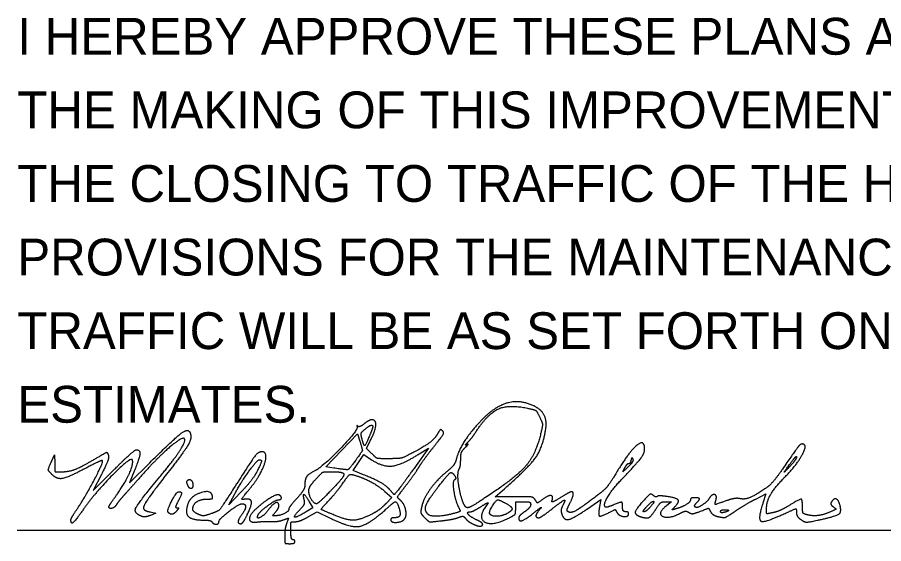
# Model space of a CAD drawing. Extents: x 0 to 34, y 0 to 22.
# Drawn here: x 24.528 to 27.822, y 8.875 to 10.877 of the extents above; entities that cross this region are included whole.
import ezdxf

# ---------------------------------------------------------------- set-up
doc = ezdxf.new("R2010")
doc.units = 0
for name, color, linetype in [('Default', 7, 'Continuous'), ('SH_Data', 7, 'Continuous'), ('SH_Text', 7, 'Continuous')]:
    doc.layers.add(name, color=color, linetype=linetype)

msp = doc.modelspace()

# ---------------------------------------------------------------- linework, layer by layer
at = {"layer": 'SH_Data'}
for p, q in [((24.5279, 10.875), (24.5279, 10.875)), ((24.5279, 8.9262), (28.0279, 8.9262))]:
    msp.add_line(p, q, dxfattribs=at)
at = {"layer": 'SH_Text'}
for p, q in [((26.8689, 9.1973), (26.8689, 9.1973)), ((25.1751, 9.0992), (25.1751, 9.0992)), ((25.1019, 8.9934), (25.1019, 8.9934)), ((24.7317, 8.9651), (24.7317, 8.9651))]:
    msp.add_line(p, q, dxfattribs=at)
for points in [[(25.7311, 9.1626), (25.7007, 9.1675), (25.8216, 9.2932), (25.8311, 9.2611)], [(25.875, 9.2176), (25.8551, 9.2374), (25.871, 9.2686)], [(26.0555, 9.216), (26.0906, 9.2382), (26.0439, 9.1722)], [(24.6592, 9.1901), (24.6697, 9.2129), (24.6703, 9.1806)], [(25.8445, 9.1369), (25.8042, 9.1532), (25.8247, 9.1836), (25.8451, 9.214), (25.8709, 9.1963)], [(24.9721, 9.1501), (24.9542, 9.1065), (25.0311, 9.1825)], [(24.8476, 9.1381), (24.8164, 9.0774), (24.8939, 9.1547)], [(25.3777, 9.0705), (25.3323, 9.0229), (25.3531, 9.0616)], [(25.9249, 9.0738), (25.9515, 9.0509), (25.9287, 9.0267)], [(26.4173, 9.0533), (26.3452, 9.0533), (26.3799, 9.0837)], [(27.3354, 9.0445), (27.3741, 9.0638), (27.3627, 9.029)], [(25.6378, 9.034), (25.6509, 9.011), (25.6264, 8.9961)], [(26.6962, 9.0079), (26.7465, 9.0423), (26.7416, 9.0164)], [(26.9947, 9.0341), (27.0155, 9.034), (26.9972, 9.0199)], [(25.0325, 8.9956), (25.0547, 8.9911), (25.0339, 8.9825)], [(25.6352, 8.9775), (25.6685, 8.9965), (25.7143, 8.9736)]]:
    msp.add_lwpolyline(points, dxfattribs=at)
for points in [[(26.2669, 9.2933), (26.314, 9.3669), (26.3945, 9.4057), (26.4679, 9.3901)], [(26.4949, 9.397), (26.4381, 9.4254), (26.3327, 9.3913), (26.2751, 9.3257)], [(26.4679, 9.3901), (26.4955, 9.3842), (26.5034, 9.3783), (26.5139, 9.3563)], [(26.5366, 9.3079), (26.542, 9.3407), (26.522, 9.3834), (26.4949, 9.397)], [(26.5139, 9.3563), (26.5247, 9.3335), (26.5252, 9.324), (26.5176, 9.2922)], [(25.8227, 9.3215), (25.8197, 9.3245), (25.8184, 9.3232), (25.8198, 9.3187)], [(25.8472, 9.331), (25.8367, 9.3227), (25.8257, 9.3185), (25.8227, 9.3215)], [(25.8765, 9.3459), (25.8708, 9.3459), (25.8576, 9.3392), (25.8472, 9.331)], [(25.8492, 9.3097), (25.8651, 9.3225), (25.8793, 9.3272), (25.8793, 9.3195)], [(25.871, 9.2686), (25.8893, 9.3044), (25.8923, 9.3459), (25.8765, 9.3459)], [(26.2751, 9.3257), (26.2415, 9.2876), (26.2035, 9.2238), (26.1959, 9.1927)], [(25.0311, 9.1825), (25.1255, 9.2758), (25.178, 9.3147), (25.1849, 9.2966)], [(25.1849, 9.2966), (25.1918, 9.2786), (25.1698, 9.2353), (25.123, 9.1749)], [(25.8198, 9.3187), (25.8234, 9.3069), (25.6903, 9.1681), (25.661, 9.1531)], [(25.8378, 9.2755), (25.8337, 9.2915), (25.8363, 9.2992), (25.8492, 9.3097)], [(25.8793, 9.3195), (25.8793, 9.3175), (25.8738, 9.3021), (25.8671, 9.2853)], [(26.1292, 9.2983), (26.1161, 9.2751), (26.0829, 9.2484), (26.0354, 9.2229)], [(26.114, 9.2467), (26.1419, 9.2815), (26.1508, 9.2978), (26.145, 9.3036)], [(26.145, 9.3036), (26.1391, 9.3094), (26.1346, 9.3078), (26.1292, 9.2983)], [(26.2403, 9.2602), (26.2487, 9.2686), (26.2606, 9.2835), (26.2669, 9.2933)], [(26.5176, 9.2922), (26.4987, 9.2135), (26.4222, 9.1255), (26.3058, 9.0486)], [(26.3799, 9.0837), (26.4722, 9.1644), (26.5256, 9.2408), (26.5366, 9.3079)], [(25.1629, 9.2744), (25.1552, 9.2822), (25.0642, 9.2052), (25.0117, 9.1464)], [(25.0698, 9.1293), (25.124, 9.1947), (25.1704, 9.267), (25.1629, 9.2744)], [(25.8311, 9.2611), (25.8403, 9.2301), (25.8397, 9.2277), (25.8158, 9.1943)], [(25.8671, 9.2853), (25.8528, 9.2495), (25.8449, 9.2468), (25.8378, 9.2755)], [(26.2365, 9.2509), (26.2302, 9.2476), (26.232, 9.2518), (26.2403, 9.2602)], [(26.9129, 9.2333), (26.9129, 9.2746), (26.8512, 9.2215), (26.8003, 9.1364)], [(24.8939, 9.1547), (24.9365, 9.1972), (24.9756, 9.2319), (24.9807, 9.2319)], [(24.9807, 9.2319), (24.9954, 9.2319), (24.9918, 9.1977), (24.9721, 9.1501)], [(25.4579, 9.2243), (25.4439, 9.2243), (25.4181, 9.1907), (25.3504, 9.0846)], [(25.4529, 9.1444), (25.4717, 9.18), (25.4745, 9.2243), (25.4579, 9.2243)], [(26.0557, 9.1674), (26.0662, 9.1842), (26.0925, 9.2199), (26.114, 9.2467)], [(26.2136, 9.1955), (26.2137, 9.2147), (26.2192, 9.2291), (26.2308, 9.2403)], [(26.2308, 9.2403), (26.2402, 9.2495), (26.2428, 9.2542), (26.2365, 9.2509)], [(26.8208, 9.1141), (26.8801, 9.1761), (26.9129, 9.2186), (26.9129, 9.2333)], [(27.5192, 9.252), (27.5095, 9.2579), (27.4896, 9.2352), (27.437, 9.1585)], [(27.4482, 9.1302), (27.487, 9.1694), (27.5309, 9.2447), (27.5192, 9.252)], [(24.6608, 9.1367), (24.6457, 9.1518), (24.6454, 9.16), (24.6592, 9.1901)], [(24.6966, 9.1483), (24.7244, 9.1483), (24.7735, 9.1679), (24.8318, 9.2023)], [(24.7591, 9.0126), (24.7889, 9.0568), (24.856, 9.1862), (24.8515, 9.1907)], [(24.9659, 9.1919), (24.9627, 9.2086), (24.829, 9.0752), (24.7795, 9.0059)], [(24.8515, 9.1907), (24.8499, 9.1922), (24.823, 9.18), (24.7917, 9.1636)], [(24.8318, 9.2023), (24.8648, 9.2217), (24.8696, 9.2228), (24.8739, 9.2115)], [(24.8739, 9.2115), (24.8769, 9.2038), (24.8665, 9.1748), (24.8476, 9.1381)], [(24.9026, 9.056), (24.9355, 9.1017), (24.9693, 9.1743), (24.9659, 9.1919)], [(25.3531, 9.0616), (25.3775, 9.107), (25.4398, 9.1937), (25.448, 9.1938)], [(25.448, 9.1938), (25.4575, 9.194), (25.4545, 9.1797), (25.4384, 9.1481)], [(25.8158, 9.1943), (25.7898, 9.1581), (25.7809, 9.1547), (25.7311, 9.1626)], [(25.8709, 9.1963), (25.9152, 9.1661), (25.9894, 9.174), (26.0555, 9.216)], [(25.9422, 9.198), (25.9012, 9.1977), (25.8923, 9.2003), (25.875, 9.2176)], [(26.0354, 9.2229), (25.998, 9.2028), (25.9808, 9.1982), (25.9422, 9.198)], [(26.1959, 9.1927), (26.1932, 9.1815), (26.1771, 9.1615), (26.1602, 9.1481)], [(26.2073, 9.1575), (26.2107, 9.1629), (26.2135, 9.18), (26.2136, 9.1955)], [(26.8504, 9.167), (26.8634, 9.1792), (26.8717, 9.1928), (26.8689, 9.1973)], [(26.8612, 9.192), (26.8598, 9.1847), (26.8556, 9.1787), (26.8518, 9.1787)], [(26.8689, 9.1973), (26.8659, 9.202), (26.8628, 9.1999), (26.8612, 9.192)], [(27.4905, 9.2041), (27.4905, 9.2003), (27.4799, 9.1853), (27.4669, 9.1708)], [(27.474, 9.1892), (27.4831, 9.2013), (27.4905, 9.208), (27.4905, 9.2041)], [(24.7917, 9.1636), (24.7224, 9.1273), (24.6791, 9.1184), (24.6608, 9.1367)], [(24.6703, 9.1806), (24.6709, 9.1491), (24.6716, 9.1483), (24.6966, 9.1483)], [(25.123, 9.1749), (25.0453, 9.0746), (25.005, 9.0163), (25.0077, 9.0082)], [(26.0439, 9.1722), (26.0182, 9.1359), (25.9898, 9.0968), (25.9808, 9.0854)], [(26.0037, 9.094), (26.0218, 9.1176), (26.0452, 9.1506), (26.0557, 9.1674)], [(26.2226, 9.0324), (26.2103, 9.0639), (26.2002, 9.1464), (26.2073, 9.1575)], [(26.8359, 9.1617), (26.8284, 9.1476), (26.8309, 9.1485), (26.8504, 9.167)], [(26.8518, 9.1787), (26.8481, 9.1787), (26.841, 9.1711), (26.8359, 9.1617)], [(27.437, 9.1585), (27.4165, 9.1286), (27.3903, 9.0974), (27.3786, 9.0892)], [(27.4669, 9.1708), (27.4423, 9.1435), (27.4454, 9.1514), (27.474, 9.1892)], [(25.0117, 9.1464), (24.981, 9.1121), (24.9457, 9.0725), (24.9331, 9.0585)], [(25.0022, 8.9781), (24.9695, 8.9907), (24.9865, 9.0288), (25.0698, 9.1293)], [(25.4384, 9.1481), (25.43, 9.1316), (25.4027, 9.0967), (25.3777, 9.0705)], [(25.4064, 9.0775), (25.4232, 9.0976), (25.4442, 9.1277), (25.4529, 9.1444)], [(25.661, 9.1531), (25.6343, 9.1394), (25.6209, 9.1201), (25.6209, 9.0954)], [(25.6624, 9.1198), (25.6859, 9.1454), (25.6924, 9.1483), (25.7265, 9.1483)], [(25.7692, 9.1405), (25.7719, 9.1363), (25.751, 9.1089), (25.7228, 9.0797)], [(25.7265, 9.1483), (25.7473, 9.1483), (25.7666, 9.1448), (25.7692, 9.1405)], [(25.7655, 9.1047), (25.7857, 9.1336), (25.794, 9.1399), (25.8066, 9.1363)], [(25.8066, 9.1363), (25.8423, 9.1258), (25.9, 9.0954), (25.9249, 9.0738)], [(25.9478, 9.076), (25.9341, 9.0925), (25.8906, 9.1181), (25.8445, 9.1369)], [(26.1602, 9.1481), (26.124, 9.1194), (26.0709, 9.0441), (26.0646, 9.0125)], [(26.1206, 9.0808), (26.1633, 9.1367), (26.1805, 9.1497), (26.1907, 9.1333)], [(26.1907, 9.1333), (26.1951, 9.1262), (26.1948, 9.1203), (26.1898, 9.1172)], [(26.8003, 9.1364), (26.7778, 9.0988), (26.756, 9.0753), (26.7156, 9.0449)], [(27.3765, 9.0083), (27.3765, 9.0353), (27.409, 9.0906), (27.4482, 9.1302)], [(25.1751, 9.0992), (25.1727, 9.1057), (25.1725, 9.1129), (25.1749, 9.1152)], [(25.1749, 9.1152), (25.1815, 9.1219), (25.1953, 9.1106), (25.1953, 9.0985)], [(25.1953, 9.0985), (25.1953, 9.0839), (25.1808, 9.0844), (25.1751, 9.0992)], [(25.6209, 9.0954), (25.6209, 9.0867), (25.6072, 9.0647), (25.5905, 9.0466)], [(25.6362, 9.0759), (25.6362, 9.0844), (25.648, 9.1041), (25.6624, 9.1198)], [(25.7132, 9.04), (25.728, 9.0557), (25.7516, 9.0848), (25.7655, 9.1047)], [(25.982, 9.0419), (25.9725, 9.0497), (25.9757, 9.0574), (26.0037, 9.094)], [(26.1898, 9.1172), (26.1814, 9.112), (26.1938, 9.0351), (26.207, 9.01)], [(26.7634, 9.014), (26.755, 9.0225), (26.7877, 9.0795), (26.8208, 9.1141)], [(24.9331, 9.0585), (24.9206, 9.0444), (24.9076, 9.0281), (24.9042, 9.0222)], [(25.1019, 8.9934), (25.0956, 8.9997), (25.1327, 9.0723), (25.1422, 9.0723)], [(25.1422, 9.0723), (25.1529, 9.0723), (25.1515, 9.0598), (25.1381, 9.0339)], [(25.2695, 9.0565), (25.2643, 9.0814), (25.1853, 9.0549), (25.1758, 9.0251)], [(25.3504, 9.0846), (25.3028, 9.0101), (25.2928, 8.9988), (25.2654, 8.9891)], [(25.3891, 9.0433), (25.3799, 9.0416), (25.3852, 9.052), (25.4064, 9.0775)], [(25.5232, 9.0602), (25.5159, 9.0648), (25.4587, 9.0296), (25.4324, 9.0042)], [(25.521, 9.0419), (25.5312, 9.0419), (25.5327, 9.0544), (25.5232, 9.0602)], [(25.6188, 9.0415), (25.6128, 9.0644), (25.6228, 9.0605), (25.6378, 9.034)], [(25.6657, 9.0267), (25.6558, 9.0267), (25.6361, 9.0595), (25.6362, 9.0759)], [(25.7228, 9.0797), (25.6947, 9.0506), (25.669, 9.0267), (25.6657, 9.0267)], [(25.9808, 9.0854), (25.9619, 9.0614), (25.9603, 9.0609), (25.9478, 9.076)], [(26.0896, 8.9862), (26.0751, 9.0006), (26.0869, 9.0366), (26.1206, 9.0808)], [(26.6345, 9.0723), (26.6318, 9.0723), (26.6131, 9.0622), (26.593, 9.0498)], [(26.6274, 9.0256), (26.6396, 9.0493), (26.6431, 9.0723), (26.6345, 9.0723)], [(26.9456, 9.0583), (26.9373, 9.0652), (26.9296, 9.061), (26.9088, 9.0383)], [(26.9608, 9.0543), (26.9582, 9.0517), (26.9514, 9.0536), (26.9456, 9.0583)], [(27.1843, 9.0419), (27.1889, 9.0596), (27.1683, 9.0635), (27.1584, 9.0469)], [(27.3786, 9.0892), (27.3378, 9.0604), (27.2931, 9.0416), (27.2758, 9.0459)], [(24.8761, 9.0153), (24.8761, 9.0174), (24.888, 9.0357), (24.9026, 9.056)], [(25.1381, 9.0339), (25.1303, 9.0187), (25.1293, 9.0115), (25.1353, 9.0115)], [(25.1953, 9.0064), (25.1953, 9.0237), (25.2245, 9.0444), (25.2489, 9.0444)], [(25.2489, 9.0444), (25.2659, 9.0444), (25.2713, 9.0476), (25.2695, 9.0565)], [(25.2941, 8.9577), (25.2941, 8.9675), (25.3699, 9.0267), (25.3825, 9.0267)], [(25.3825, 9.0267), (25.3961, 9.0267), (25.3954, 9.0041), (25.3813, 8.9854)], [(25.4023, 8.9852), (25.4205, 9.0228), (25.4148, 9.048), (25.3891, 9.0433)], [(25.4432, 8.9839), (25.448, 8.9956), (25.5101, 9.0419), (25.521, 9.0419)], [(25.5221, 9.0178), (25.5221, 9.0344), (25.4998, 9.0268), (25.4834, 9.0045)], [(25.5905, 9.0466), (25.5738, 9.0285), (25.5601, 9.0103), (25.5601, 9.0062)], [(25.6015, 9.0035), (25.616, 9.0186), (25.6216, 9.0309), (25.6188, 9.0415)], [(25.7394, 8.9808), (25.6842, 9.003), (25.6822, 9.0073), (25.7132, 9.04)], [(25.9287, 9.0267), (25.9162, 9.0134), (25.8929, 8.9958), (25.8769, 8.9876)], [(25.9307, 9.007), (25.9473, 9.022), (25.9628, 9.0343), (25.965, 9.0343)], [(25.965, 9.0343), (25.9717, 9.0343), (25.9859, 8.9875), (25.9814, 8.9802)], [(25.9998, 8.9683), (26.01, 8.9806), (25.9984, 9.0282), (25.982, 9.0419)], [(26.2403, 9.0115), (26.235, 9.0115), (26.2271, 9.0209), (26.2226, 9.0324)], [(26.3058, 9.0486), (26.275, 9.0282), (26.2455, 9.0115), (26.2403, 9.0115)], [(26.2918, 9.0166), (26.3094, 9.0277), (26.3202, 9.032), (26.3156, 9.0261)], [(26.3156, 9.0261), (26.2768, 8.976), (26.3306, 8.9399), (26.3961, 8.9721)], [(26.324, 8.9885), (26.3201, 8.9949), (26.3483, 9.0419), (26.3561, 9.0419)], [(26.3561, 9.0419), (26.3576, 9.0419), (26.369, 9.0367), (26.3813, 9.0303)], [(26.3813, 9.0303), (26.4071, 9.017), (26.4102, 9.0003), (26.389, 8.989)], [(26.4974, 9.0408), (26.4909, 9.051), (26.4761, 9.0533), (26.4173, 9.0533)], [(26.4227, 9.0079), (26.4227, 9.033), (26.4244, 9.0343), (26.4569, 9.0343)], [(26.4569, 9.0343), (26.4716, 9.0343), (26.4797, 9.0305), (26.4797, 9.0234)], [(26.526, 9.0436), (26.507, 9.0296), (26.5046, 9.0293), (26.4974, 9.0408)], [(26.5604, 9.0376), (26.5674, 9.0559), (26.5473, 9.0594), (26.526, 9.0436)], [(26.5566, 9.0039), (26.5993, 9.0376), (26.6138, 9.0425), (26.6012, 9.0188)], [(26.593, 9.0498), (26.5729, 9.0374), (26.5582, 9.0319), (26.5604, 9.0376)], [(26.6194, 8.9985), (26.6172, 9.0007), (26.6208, 9.0129), (26.6274, 9.0256)], [(26.7156, 9.0449), (26.6646, 9.0066), (26.6287, 8.9892), (26.6194, 8.9985)], [(26.8293, 9.0102), (26.8293, 9.0318), (26.8227, 9.0339), (26.7937, 9.0218)], [(26.9088, 9.0383), (26.8792, 9.0059), (26.8753, 8.9844), (26.8977, 8.9773)], [(26.9205, 9.0153), (26.9414, 9.0375), (26.9523, 9.034), (26.932, 9.0116)], [(26.9567, 9.0077), (26.9695, 9.0276), (26.9791, 9.0343), (26.9947, 9.0341)], [(27, 9.0538), (26.981, 9.0566), (26.9633, 9.0568), (26.9608, 9.0543)], [(27.025, 9.0122), (27.0452, 9.0333), (27.0361, 9.0483), (27, 9.0538)], [(27.0877, 9.0428), (27.0877, 9.0342), (27.059, 9.0154), (27.0345, 9.008)], [(27.1029, 9.0495), (27.0946, 9.0495), (27.0877, 9.0465), (27.0877, 9.0428)], [(27.1091, 9.0284), (27.1224, 9.0416), (27.1201, 9.0495), (27.1029, 9.0495)], [(27.1051, 9.0144), (27.1024, 9.0171), (27.1042, 9.0234), (27.1091, 9.0284)], [(27.1584, 9.0469), (27.1496, 9.0322), (27.1109, 9.0086), (27.1051, 9.0144)], [(27.2255, 9.0385), (27.1827, 9.0234), (27.1795, 9.0236), (27.1843, 9.0419)], [(27.2758, 9.0459), (27.2664, 9.0483), (27.2438, 9.0449), (27.2255, 9.0385)], [(27.2575, 8.9986), (27.2791, 9.0132), (27.3141, 9.0339), (27.3354, 9.0445)], [(27.3627, 9.029), (27.3427, 8.9682), (27.3666, 8.9533), (27.4344, 8.9844)], [(27.5133, 9.0112), (27.5133, 9.0433), (27.5035, 9.045), (27.4624, 9.0201)], [(27.5817, 8.9662), (27.6432, 8.9798), (27.6633, 8.9971), (27.6536, 9.0278)], [(27.6228, 9.0332), (27.6198, 9.0283), (27.623, 9.0203), (27.6298, 9.0153)], [(27.6536, 9.0278), (27.6486, 9.0436), (27.6311, 9.0466), (27.6228, 9.0332)], [(24.7317, 8.9651), (24.7317, 8.9689), (24.7441, 8.9903), (24.7591, 9.0126)], [(24.7795, 9.0059), (24.7483, 8.9621), (24.7317, 8.948), (24.7317, 8.9651)], [(24.9042, 9.0222), (24.8986, 9.0123), (24.8761, 9.0067), (24.8761, 9.0153)], [(25.0077, 9.0082), (25.0092, 9.0037), (25.0203, 8.9981), (25.0325, 8.9956)], [(25.1345, 9.0001), (25.1247, 8.9883), (25.1101, 8.9853), (25.1019, 8.9934)], [(25.1353, 9.0115), (25.1415, 9.0115), (25.1413, 9.0083), (25.1345, 9.0001)], [(25.1758, 9.0251), (25.165, 8.9909), (25.1922, 8.9644), (25.2381, 8.9644)], [(25.2149, 8.9871), (25.2041, 8.992), (25.1953, 9.0007), (25.1953, 9.0064)], [(25.4324, 9.0042), (25.4087, 8.9814), (25.4123, 8.9536), (25.4385, 8.957)], [(25.4834, 9.0045), (25.4672, 8.9827), (25.4361, 8.9667), (25.4432, 8.9839)], [(25.5092, 8.9811), (25.4981, 8.9811), (25.4981, 8.9824), (25.5095, 8.995)], [(25.5601, 9.0062), (25.5601, 8.9975), (25.5269, 8.9811), (25.5092, 8.9811)], [(25.5095, 8.995), (25.5165, 9.0027), (25.5221, 9.0129), (25.5221, 9.0178)], [(25.6264, 8.9961), (25.5892, 8.9734), (25.5763, 8.9772), (25.6015, 9.0035)], [(25.7143, 8.9736), (25.7919, 8.9349), (25.863, 8.9458), (25.9307, 9.007)], [(26.0646, 9.0125), (26.0612, 8.9958), (26.0643, 8.9861), (26.077, 8.9734)], [(26.207, 9.01), (26.2126, 8.9993), (26.2088, 8.9957), (26.1853, 8.9891)], [(26.2728, 8.9659), (26.2488, 8.9773), (26.2353, 8.9963), (26.2512, 8.9963)], [(26.2512, 8.9963), (26.2558, 8.9963), (26.2741, 9.0054), (26.2918, 9.0166)], [(26.3961, 8.9721), (26.4176, 8.9827), (26.4227, 8.9895), (26.4227, 9.0079)], [(26.4569, 8.9963), (26.4444, 8.9874), (26.4341, 8.9769), (26.4341, 8.973)], [(26.4341, 8.973), (26.4341, 8.9578), (26.4607, 8.9672), (26.4941, 8.994)], [(26.4797, 9.0234), (26.4797, 9.0174), (26.4695, 9.0052), (26.4569, 8.9963)], [(26.4941, 8.994), (26.5134, 9.0095), (26.5231, 9.0152), (26.5158, 9.0067)], [(26.5158, 9.0067), (26.501, 8.9896), (26.4984, 8.9735), (26.5103, 8.9735)], [(26.5103, 8.9735), (26.5146, 8.9735), (26.5355, 8.9872), (26.5566, 9.0039)], [(26.6012, 9.0188), (26.5966, 9.0103), (26.595, 8.9966), (26.5976, 8.9884)], [(26.5976, 8.9884), (26.6057, 8.963), (26.6408, 8.97), (26.6962, 9.0079)], [(26.7416, 9.0164), (26.7355, 8.9836), (26.7458, 8.9768), (26.777, 8.993)], [(26.7937, 9.0218), (26.7789, 9.0157), (26.7653, 9.0122), (26.7634, 9.014)], [(26.777, 8.993), (26.7992, 9.0044), (26.8018, 9.0045), (26.808, 8.9933)], [(26.808, 8.9933), (26.8154, 8.9801), (26.8521, 8.9763), (26.8521, 8.9887)], [(26.8407, 8.9963), (26.8344, 8.9963), (26.8293, 9.0026), (26.8293, 9.0102)], [(26.8521, 8.9887), (26.8521, 8.9929), (26.847, 8.9963), (26.8407, 8.9963)], [(26.8977, 8.9773), (26.921, 8.9699), (26.9379, 8.9786), (26.9567, 9.0077)], [(26.9104, 8.9963), (26.9062, 8.9963), (26.9107, 9.0048), (26.9205, 9.0153)], [(26.932, 9.0116), (26.9244, 9.0032), (26.9147, 8.9963), (26.9104, 8.9963)], [(26.9972, 9.0199), (26.9595, 8.9909), (27.0032, 8.967), (27.0497, 8.9912)], [(27.0345, 9.008), (27.019, 9.0033), (27.0172, 9.004), (27.025, 9.0122)], [(27.0497, 8.9912), (27.0629, 8.9981), (27.0726, 8.9988), (27.0814, 8.9935)], [(27.0814, 8.9935), (27.0903, 8.9881), (27.1031, 8.9895), (27.1251, 8.9981)], [(27.1251, 8.9981), (27.1545, 9.0097), (27.1566, 9.0096), (27.1637, 8.9963)], [(27.1637, 8.9963), (27.1678, 8.9886), (27.1818, 8.98), (27.1948, 8.9772)], [(27.1948, 8.9772), (27.2141, 8.9729), (27.2254, 8.9768), (27.2575, 8.9986)], [(27.2017, 8.997), (27.2017, 9.0008), (27.2086, 9.0039), (27.2169, 9.0039)], [(27.2169, 8.9941), (27.2086, 8.9919), (27.2017, 8.9932), (27.2017, 8.997)], [(27.2169, 9.0039), (27.2253, 9.0039), (27.2321, 9.0026), (27.2321, 9.001)], [(27.2321, 9.001), (27.2321, 8.9994), (27.2253, 8.9963), (27.2169, 8.9941)], [(27.4012, 8.9927), (27.3781, 8.9878), (27.3765, 8.9888), (27.3765, 9.0083)], [(27.4624, 9.0201), (27.4424, 9.0079), (27.4148, 8.9956), (27.4012, 8.9927)], [(27.4344, 8.9844), (27.4846, 9.0073), (27.4905, 9.0081), (27.4905, 8.9914)], [(27.5324, 8.9842), (27.5175, 8.988), (27.5133, 8.9938), (27.5133, 9.0112)], [(27.6241, 8.9979), (27.5963, 8.9853), (27.5536, 8.9789), (27.5324, 8.9842)], [(27.6298, 9.0153), (27.641, 9.0072), (27.6404, 9.0054), (27.6241, 8.9979)], [(25.0339, 8.9825), (25.0224, 8.9778), (25.0082, 8.9758), (25.0022, 8.9781)], [(25.2654, 8.9891), (25.2409, 8.9805), (25.2303, 8.98), (25.2149, 8.9871)], [(25.2381, 8.9644), (25.2522, 8.9644), (25.2657, 8.9613), (25.268, 8.9576)], [(25.3813, 8.9854), (25.3684, 8.9683), (25.3666, 8.9507), (25.3778, 8.9507)], [(25.3778, 8.9507), (25.382, 8.9507), (25.3931, 8.9662), (25.4023, 8.9852)], [(25.4892, 8.9589), (25.5067, 8.9585), (25.5296, 8.9615), (25.5402, 8.9656)], [(25.5402, 8.9656), (25.5586, 8.9725), (25.5592, 8.972), (25.5522, 8.9537)], [(25.5848, 8.9584), (25.5942, 8.9585), (25.6169, 8.9671), (25.6352, 8.9775)], [(25.8769, 8.9876), (25.8337, 8.9654), (25.7838, 8.9629), (25.7394, 8.9808)], [(25.9625, 8.9735), (25.9544, 8.9735), (25.9477, 8.9701), (25.9477, 8.9659)], [(25.9477, 8.9659), (25.9477, 8.9547), (25.9901, 8.9567), (25.9998, 8.9683)], [(25.9814, 8.9802), (25.9791, 8.9765), (25.9706, 8.9735), (25.9625, 8.9735)], [(26.077, 8.9734), (26.0921, 8.9583), (26.0987, 8.9571), (26.1393, 8.9617)], [(26.1853, 8.9891), (26.1531, 8.9802), (26.0973, 8.9785), (26.0896, 8.9862)], [(26.1393, 8.9617), (26.1643, 8.9645), (26.1934, 8.9701), (26.204, 8.9741)], [(26.204, 8.9741), (26.2182, 8.9796), (26.2254, 8.9787), (26.2318, 8.9708)], [(26.2318, 8.9708), (26.2365, 8.965), (26.2472, 8.9565), (26.2555, 8.9519)], [(26.2972, 8.9488), (26.2971, 8.9519), (26.2861, 8.9596), (26.2728, 8.9659)], [(26.389, 8.989), (26.3704, 8.979), (26.3301, 8.9788), (26.324, 8.9885)], [(27.4905, 8.9914), (27.4905, 8.9846), (27.4965, 8.9744), (27.5038, 8.9689)], [(27.5038, 8.9689), (27.5198, 8.9568), (27.5363, 8.9562), (27.5817, 8.9662)], [(25.268, 8.9576), (25.2735, 8.9486), (25.2941, 8.9487), (25.2941, 8.9577)], [(25.4385, 8.957), (25.449, 8.9584), (25.4718, 8.9592), (25.4892, 8.9589)], [(25.5522, 8.9537), (25.5482, 8.9432), (25.5449, 8.9211), (25.5449, 8.9046)], [(25.5677, 8.9241), (25.5677, 8.9545), (25.5696, 8.9583), (25.5848, 8.9584)], [(26.2555, 8.9519), (26.2731, 8.9423), (26.2974, 8.9405), (26.2972, 8.9488)], [(25.5449, 8.9046), (25.5449, 8.8778), (25.5469, 8.8747), (25.5639, 8.8747)], [(25.5753, 8.8899), (25.5711, 8.8899), (25.5677, 8.9053), (25.5677, 8.9241)], [(25.5639, 8.8747), (25.5744, 8.8747), (25.5829, 8.8781), (25.5829, 8.8823)], [(25.5829, 8.8823), (25.5829, 8.8865), (25.5795, 8.8899), (25.5753, 8.8899)]]:
    msp.add_open_spline(points, degree=2, dxfattribs=at)

# ---------------------------------------------------------------- texts
at = {"layer": 'Default'}
for s, p in [('I HEREBY APPROVE THESE PLANS AND DECLARE THAT ', (24.5279, 10.735)), ('THE MAKING OF THIS IMPROVEMENT WILL NOT REQUIRE', (24.5279, 10.455)), ('THE CLOSING TO TRAFFIC OF THE HIGHWAY AND THAT', (24.5279, 10.175)), ('PROVISIONS FOR THE MAINTENANCE AND SAFETY OF ', (24.5279, 9.895)), ('TRAFFIC WILL BE AS SET FORTH ON THE PLANS AND ', (24.5279, 9.615)), ('ESTIMATES.', (24.5279, 9.335))]:
    msp.add_text(s, height=0.14, dxfattribs=at).set_placement(p)

doc.saveas('drawing.dxf')
